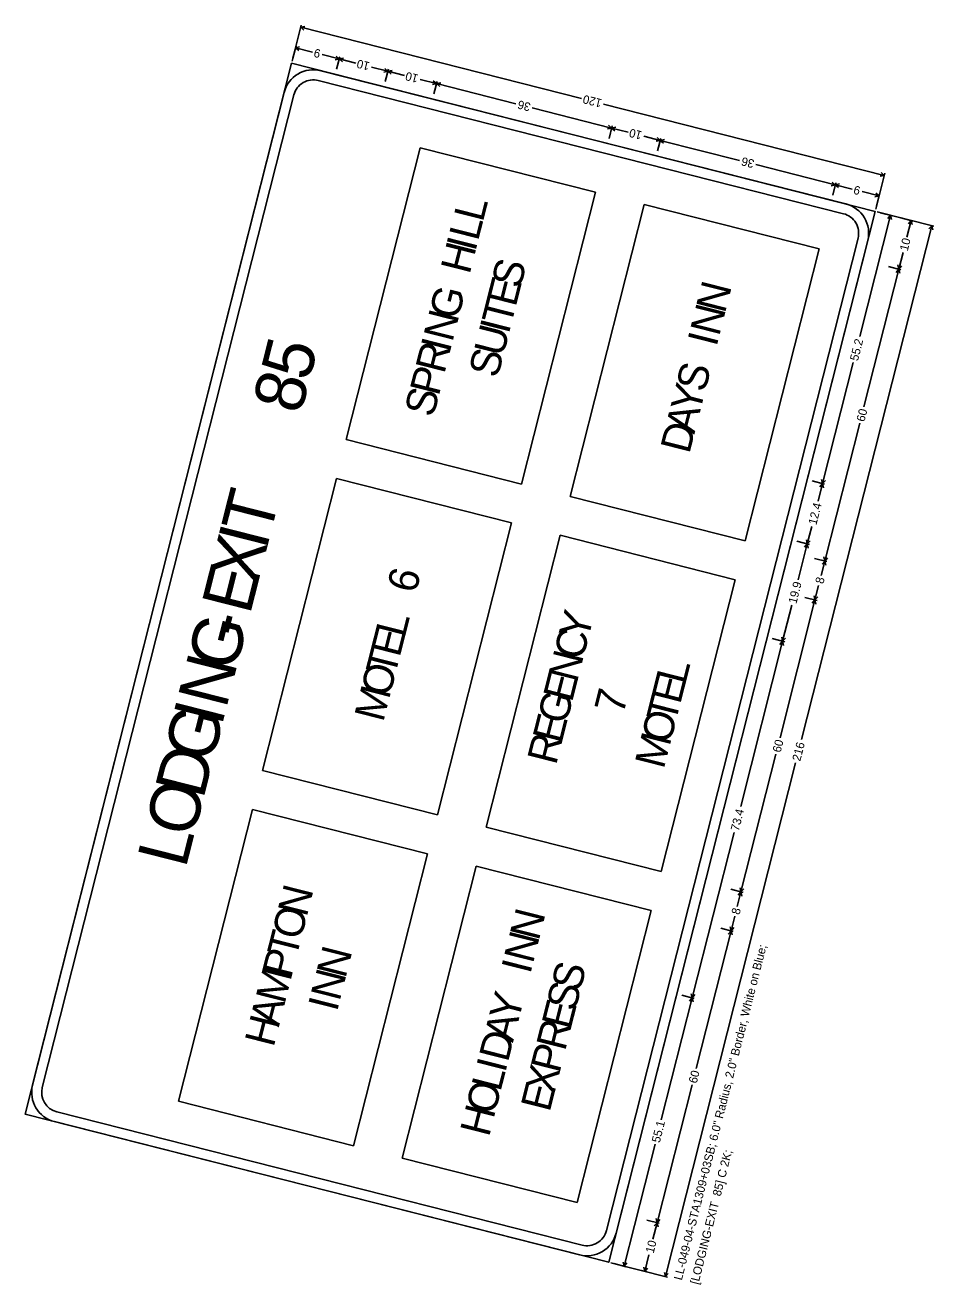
# Model space of a CAD drawing. Extents: x 670257 to 671518, y 737783 to 738188.
# Drawn here: x 670629.61 to 670656.02, y 738032.49 to 738069.09 of the extents above; entities that cross this region are included whole.
import ezdxf

# ---------------------------------------------------------------- set-up
doc = ezdxf.new("R2010")
doc.units = 0
doc.layers.add('R_SIGN', color=7, linetype='Continuous')

msp = doc.modelspace()

# ---------------------------------------------------------------- linework, layer by layer
at = {"layer": 'R_SIGN'}
for p, q in [((670637.631, 738069.092), (670637.366, 738068.045)), ((670637.736, 738069.059), (670637.616, 738069.032)), ((670645.776, 738066.963), (670637.616, 738069.032)), ((670637.709, 738068.952), (670637.616, 738069.032)), ((670637.479, 738068.494), (670637.388, 738068.135)), ((670637.585, 738068.461), (670637.464, 738068.434)), ((670637.958, 738068.309), (670637.464, 738068.434)), ((670637.558, 738068.354), (670637.464, 738068.434)), ((670638.242, 738068.237), (670638.736, 738068.112)), ((670638.616, 738068.085), (670638.736, 738068.112)), ((670638.643, 738068.192), (670638.736, 738068.112)), ((670638.752, 738068.171), (670638.66, 738067.812)), ((670638.857, 738068.138), (670638.736, 738068.112)), ((670639.217, 738067.99), (670638.736, 738068.112)), ((670638.83, 738068.031), (670638.736, 738068.112)), ((670639.669, 738067.875), (670640.15, 738067.753)), ((670640.029, 738067.727), (670640.15, 738067.753)), ((670640.057, 738067.834), (670640.15, 738067.753)), ((670640.165, 738067.813), (670640.074, 738067.454)), ((670640.271, 738067.779), (670640.15, 738067.753)), ((670640.631, 738067.631), (670640.15, 738067.753)), ((670640.243, 738067.672), (670640.15, 738067.753)), ((670641.083, 738067.516), (670641.564, 738067.395)), ((670641.443, 738067.368), (670641.564, 738067.395)), ((670641.47, 738067.475), (670641.564, 738067.395)), ((670641.579, 738067.454), (670641.488, 738067.095)), ((670641.684, 738067.421), (670641.564, 738067.395)), ((670643.87, 738066.81), (670641.564, 738067.395)), ((670641.657, 738067.314), (670641.564, 738067.395)), ((670644.346, 738066.689), (670646.652, 738066.104)), ((670646.419, 738066.8), (670654.579, 738064.73)), ((670646.559, 738066.185), (670646.652, 738066.104)), ((670646.532, 738066.078), (670646.652, 738066.104)), ((670646.668, 738066.164), (670646.577, 738065.805)), ((670646.773, 738066.13), (670646.652, 738066.104)), ((670647.133, 738065.982), (670646.652, 738066.104)), ((670646.746, 738066.023), (670646.652, 738066.104)), ((670647.585, 738065.867), (670648.066, 738065.745)), ((670647.973, 738065.826), (670648.066, 738065.745)), ((670648.081, 738065.805), (670647.99, 738065.446)), ((670638.94, 738057.051), (670641.091, 738065.532)), ((670641.091, 738065.532), (670646.18, 738064.242)), ((670647.945, 738065.719), (670648.066, 738065.745)), ((670648.187, 738065.772), (670648.066, 738065.745)), ((670650.372, 738065.16), (670648.066, 738065.745)), ((670648.159, 738065.665), (670648.066, 738065.745)), ((670650.849, 738065.04), (670653.155, 738064.455)), ((670654.594, 738064.79), (670654.328, 738063.743)), ((670654.458, 738064.704), (670654.579, 738064.73)), ((670654.485, 738064.811), (670654.579, 738064.73)), ((670653.034, 738064.428), (670653.155, 738064.455)), ((670653.061, 738064.535), (670653.155, 738064.455)), ((670653.17, 738064.514), (670653.079, 738064.156)), ((670653.17, 738064.514), (670653.079, 738064.156)), ((670653.275, 738064.481), (670653.155, 738064.455)), ((670653.649, 738064.329), (670653.155, 738064.455)), ((670653.248, 738064.374), (670653.155, 738064.455)), ((670646.18, 738064.242), (670644.029, 738055.76)), ((670653.933, 738064.257), (670654.427, 738064.132)), ((670654.307, 738064.106), (670654.427, 738064.132)), ((670654.334, 738064.213), (670654.427, 738064.132)), ((670654.442, 738064.192), (670654.351, 738063.833)), ((670645.443, 738055.402), (670647.594, 738063.883)), ((670647.594, 738063.883), (670652.683, 738062.592)), ((670656.018, 738063.251), (670654.373, 738063.668)), ((670654.822, 738063.554), (670654.463, 738063.645)), ((670652.172, 738048.336), (670655.959, 738063.266)), ((670653.87, 738060.052), (670654.762, 738063.57)), ((670654.681, 738063.476), (670654.762, 738063.57)), ((670654.788, 738063.449), (670654.762, 738063.57)), ((670655.42, 738063.403), (670655.061, 738063.494)), ((670655.238, 738062.937), (670655.36, 738063.418)), ((670655.28, 738063.324), (670655.36, 738063.418)), ((670655.387, 738063.297), (670655.36, 738063.418)), ((670655.878, 738063.173), (670655.959, 738063.266)), ((670655.985, 738063.146), (670655.959, 738063.266)), ((670652.683, 738062.592), (670650.531, 738054.111)), ((670655.124, 738062.485), (670655.002, 738062.004)), ((670653.986, 738058.001), (670655.002, 738062.004)), ((670655.062, 738061.989), (670654.703, 738062.08)), ((670655.062, 738061.989), (670654.703, 738062.08)), ((670654.921, 738061.911), (670655.002, 738062.004)), ((670654.975, 738062.125), (670655.002, 738062.004)), ((670655.082, 738062.098), (670655.002, 738062.004)), ((670655.028, 738061.884), (670655.002, 738062.004)), ((670653.677, 738059.291), (670652.785, 738055.774)), ((670653.866, 738057.526), (670652.851, 738053.523)), ((670644.029, 738055.76), (670638.94, 738057.051)), ((670636.502, 738047.438), (670638.653, 738055.92)), ((670638.653, 738055.92), (670643.742, 738054.629)), ((670652.845, 738055.759), (670652.486, 738055.85)), ((670652.845, 738055.759), (670652.486, 738055.85)), ((670652.656, 738055.266), (670652.785, 738055.774)), ((670652.704, 738055.68), (670652.785, 738055.774)), ((670652.758, 738055.894), (670652.785, 738055.774)), ((670652.865, 738055.867), (670652.785, 738055.774)), ((670652.811, 738055.653), (670652.785, 738055.774)), ((670650.531, 738054.111), (670645.443, 738055.402)), ((670643.742, 738054.629), (670641.591, 738046.148)), ((670652.469, 738054.528), (670652.34, 738054.021)), ((670643.005, 738045.789), (670645.156, 738054.271)), ((670645.156, 738054.271), (670650.245, 738052.98)), ((670652.4, 738054.006), (670652.041, 738054.097)), ((670652.314, 738054.141), (670652.34, 738054.021)), ((670652.421, 738054.114), (670652.34, 738054.021)), ((670652.076, 738052.978), (670652.34, 738054.021)), ((670652.26, 738053.927), (670652.34, 738054.021)), ((670652.367, 738053.9), (670652.34, 738054.021)), ((670652.91, 738053.508), (670652.551, 738053.599)), ((670652.743, 738053.1), (670652.851, 738053.523)), ((670652.77, 738053.429), (670652.851, 738053.523)), ((670652.824, 738053.643), (670652.851, 738053.523)), ((670652.931, 738053.616), (670652.851, 738053.523)), ((670652.877, 738053.402), (670652.851, 738053.523)), ((670650.245, 738052.98), (670648.094, 738044.499)), ((670652.671, 738052.815), (670652.564, 738052.392)), ((670651.549, 738048.389), (670652.564, 738052.392)), ((670652.624, 738052.377), (670652.265, 738052.468)), ((670652.483, 738052.298), (670652.564, 738052.392)), ((670652.537, 738052.512), (670652.564, 738052.392)), ((670652.644, 738052.485), (670652.564, 738052.392)), ((670652.59, 738052.271), (670652.564, 738052.392)), ((670651.888, 738052.237), (670651.623, 738051.194)), ((670650.406, 738046.393), (670651.623, 738051.194)), ((670651.683, 738051.179), (670651.324, 738051.27)), ((670651.543, 738051.1), (670651.623, 738051.194)), ((670651.597, 738051.314), (670651.623, 738051.194)), ((670651.704, 738051.287), (670651.623, 738051.194)), ((670651.65, 738051.073), (670651.623, 738051.194)), ((670651.428, 738047.913), (670650.413, 738043.91)), ((670652.001, 738047.663), (670648.215, 738032.733)), ((670641.591, 738046.148), (670636.502, 738047.438)), ((670634.064, 738037.826), (670636.215, 738046.308)), ((670636.215, 738046.308), (670641.304, 738045.017)), ((670648.094, 738044.499), (670643.005, 738045.789)), ((670650.213, 738045.633), (670648.995, 738040.832)), ((670641.304, 738045.017), (670639.153, 738036.535)), ((670640.567, 738036.177), (670642.718, 738044.658)), ((670642.718, 738044.658), (670647.807, 738043.368)), ((670650.473, 738043.895), (670650.114, 738043.986)), ((670650.305, 738043.488), (670650.413, 738043.91)), ((670650.332, 738043.817), (670650.413, 738043.91)), ((670650.386, 738044.031), (670650.413, 738043.91)), ((670650.493, 738044.004), (670650.413, 738043.91)), ((670650.439, 738043.79), (670650.413, 738043.91)), ((670647.807, 738043.368), (670645.656, 738034.886)), ((670650.233, 738043.203), (670650.126, 738042.78)), ((670649.111, 738038.777), (670650.126, 738042.78)), ((670650.186, 738042.764), (670649.827, 738042.855)), ((670650.045, 738042.686), (670650.126, 738042.78)), ((670650.1, 738042.9), (670650.126, 738042.78)), ((670650.207, 738042.873), (670650.126, 738042.78)), ((670650.152, 738042.659), (670650.126, 738042.78)), ((670648.969, 738040.953), (670648.995, 738040.832)), ((670649.076, 738040.926), (670648.995, 738040.832)), ((670648.097, 738037.292), (670648.995, 738040.832)), ((670649.055, 738040.817), (670648.696, 738040.908)), ((670648.915, 738040.739), (670648.995, 738040.832)), ((670649.022, 738040.712), (670648.995, 738040.832)), ((670648.99, 738038.301), (670647.975, 738034.298)), ((670639.153, 738036.535), (670634.064, 738037.826)), ((670647.916, 738036.577), (670647.018, 738033.036)), ((670645.656, 738034.886), (670640.567, 738036.177)), ((670648.035, 738034.283), (670647.676, 738034.374)), ((670647.948, 738034.419), (670647.975, 738034.298)), ((670648.055, 738034.392), (670647.975, 738034.298)), ((670647.853, 738033.817), (670647.975, 738034.298)), ((670647.894, 738034.205), (670647.975, 738034.298)), ((670648.001, 738034.178), (670647.975, 738034.298)), ((670647.738, 738033.365), (670647.616, 738032.885)), ((670648.274, 738032.718), (670646.629, 738033.135)), ((670647.078, 738033.021), (670646.719, 738033.112)), ((670646.992, 738033.157), (670647.018, 738033.036)), ((670647.099, 738033.13), (670647.018, 738033.036)), ((670647.676, 738032.869), (670647.317, 738032.96)), ((670647.59, 738033.005), (670647.616, 738032.885)), ((670647.697, 738032.978), (670647.616, 738032.885)), ((670648.188, 738032.853), (670648.215, 738032.733)), ((670648.295, 738032.826), (670648.215, 738032.733))]:
    msp.add_line(p, q, dxfattribs=at)
for points in [[(670646.569, 738033.15), (670654.313, 738063.683), (670637.35, 738067.986), (670629.606, 738037.452), (670646.569, 738033.15), (670646.569, 738033.15)], [(670638.198, 738067.77), (670653.465, 738063.898)], [(670653.393, 738063.616), (670638.127, 738067.488)], [(670629.822, 738038.3), (670637.135, 738067.137)], [(670637.418, 738067.066), (670630.104, 738038.229)], [(670646.502, 738034.07), (670653.815, 738062.907)], [(670654.098, 738062.835), (670646.784, 738033.998)], [(670630.526, 738037.52), (670645.793, 738033.648)], [(670645.721, 738033.365), (670630.455, 738037.237)]]:
    msp.add_lwpolyline(points, dxfattribs=at)
for centre, radius, start, end in [((670637.983, 738066.922), 0.875, 75.7686, 165.7688), ((670637.983, 738066.922), 0.583, 75.7686, 165.7688), ((670653.25, 738063.05), 0.583, 345.7686, 75.7688), ((670653.25, 738063.05), 0.875, 345.7686, 75.7688), ((670630.67, 738038.085), 0.875, 165.7688, 255.7684), ((670630.67, 738038.085), 0.583, 165.7688, 255.7684), ((670645.936, 738034.213), 0.875, 255.7684, 345.7686), ((670645.936, 738034.213), 0.583, 255.7684, 345.7686)]:
    msp.add_arc(centre, radius, start, end, dxfattribs=at)

# ---------------------------------------------------------------- texts
for s, height, rotation, p in [('9', 0.247, 165.7688, (670638.213, 738068.372)), ('10', 0.2469, 165.7688, (670639.639, 738068.01)), ('10', 0.2469, 165.7688, (670641.053, 738067.651)), ('36', 0.2469, 165.7688, (670644.317, 738066.824)), ('120', 0.2469, 165.7688, (670646.389, 738066.935)), ('10', 0.2469, 165.7688, (670647.556, 738066.002)), ('36', 0.2469, 165.7688, (670650.819, 738065.174)), ('9', 0.247, 165.7688, (670653.903, 738064.392)), ('L', 0.875, 75.7686, (670642.907, 738063.348)), ('L', 0.875, 75.7686, (670642.767, 738062.796)), ('I', 0.875, 75.7686, (670642.689, 738062.491)), ('10', 0.2469, 75.7686, (670655.259, 738062.515)), ('H', 0.875, 75.7686, (670642.522, 738061.829)), ('S', 0.875, 75.7686, (670643.996, 738061.415)), ('E', 0.875, 75.7686, (670643.861, 738060.881)), ('G', 0.875, 75.7686, (670642.186, 738060.506)), ('N', 0.875, 75.7686, (670649.944, 738060.692)), ('T', 0.875, 75.7686, (670643.721, 738060.329)), ('N', 0.875, 75.7686, (670642.023, 738059.862)), ('N', 0.875, 75.7686, (670649.776, 738060.03)), ('U', 0.875, 75.7686, (670643.493, 738059.43)), ('I', 0.875, 75.7686, (670643.661, 738060.092)), ('5', 1.458, 75.7686, (670637.858, 738058.717)), ('I', 0.875, 75.7686, (670641.945, 738059.556)), ('I', 0.875, 75.7686, (670649.699, 738059.725)), ('55.2', 0.2469, 75.7686, (670653.812, 738059.321)), ('R', 0.875, 75.7686, (670641.788, 738058.937)), ('S', 0.875, 75.7686, (670643.336, 738058.811)), ('S', 0.875, 75.7686, (670649.363, 738058.402)), ('8', 1.458, 75.7686, (670637.614, 738057.756)), ('P', 0.875, 75.7686, (670641.625, 738058.293)), ('S', 0.875, 75.7686, (670641.468, 738057.674)), ('Y', 0.875, 75.7686, (670649.206, 738057.783)), ('A', 0.875, 75.7686, (670649.055, 738057.189)), ('60', 0.2469, 75.7686, (670654.001, 738057.555)), ('D', 0.875, 75.7686, (670648.909, 738056.612)), ('T', 1.458, 75.7686, (670636.714, 738054.208)), ('12.4', 0.2469, 75.7686, (670652.604, 738054.557)), ('I', 1.458, 75.7686, (670636.614, 738053.812)), ('X', 1.458, 75.7686, (670636.352, 738052.78)), ('E', 1.458, 75.7686, (670636.137, 738051.932)), ('6', 0.875, 75.7686, (670640.96, 738052.559)), ('8', 0.247, 75.7686, (670652.806, 738052.844)), ('19.9', 0.2469, 75.7686, (670652.023, 738052.266)), ('-', 1.458, 75.7686, (670635.962, 738051.239)), ('Y', 0.875, 75.7686, (670645.955, 738051.193)), ('G', 1.458, 75.7686, (670635.718, 738050.278)), ('E', 0.875, 75.7686, (670640.489, 738050.702)), ('L', 0.875, 75.7686, (670640.636, 738051.278)), ('C', 0.875, 75.7686, (670645.809, 738050.616)), ('T', 0.875, 75.7686, (670640.349, 738050.15)), ('N', 0.875, 75.7686, (670645.645, 738049.972)), ('N', 1.458, 75.7686, (670635.445, 738049.204)), ('O', 0.875, 75.7686, (670640.197, 738049.548)), ('L', 0.875, 75.7686, (670648.79, 738049.914)), ('E', 0.875, 75.7686, (670645.499, 738049.395)), ('E', 0.875, 75.7686, (670648.644, 738049.338)), ('M', 0.875, 75.7686, (670640.012, 738048.819)), ('7', 0.875, 75.7686, (670646.988, 738049.04)), ('I', 1.458, 75.7686, (670635.316, 738048.695)), ('G', 0.875, 75.7686, (670645.335, 738048.75)), ('T', 0.875, 75.7686, (670648.504, 738048.786)), ('G', 1.458, 75.7686, (670635.044, 738047.62)), ('E', 0.875, 75.7686, (670645.193, 738048.191)), ('O', 0.875, 75.7686, (670648.351, 738048.184)), ('R', 0.875, 75.7686, (670645.036, 738047.571)), ('M', 0.875, 75.7686, (670648.166, 738047.455)), ('60', 0.2469, 75.7686, (670651.563, 738047.943)), ('216', 0.2469, 75.7686, (670652.136, 738047.692)), ('D', 1.458, 75.7686, (670634.779, 738046.574)), ('O', 1.458, 75.7686, (670634.495, 738045.458)), ('73.4', 0.2469, 75.7686, (670650.348, 738045.662)), ('L', 1.458, 75.7686, (670634.269, 738044.567)), ('N', 0.875, 75.7686, (670637.786, 738043.156)), ('O', 0.875, 75.7686, (670637.616, 738042.486)), ('N', 0.875, 75.7686, (670644.531, 738042.465)), ('8', 0.247, 75.7686, (670650.368, 738043.232)), ('T', 0.875, 75.7686, (670637.48, 738041.952)), ('N', 0.875, 75.7686, (670644.363, 738041.804)), ('P', 0.875, 75.7686, (670637.334, 738041.375)), ('N', 0.875, 75.7686, (670638.913, 738041.372)), ('LL-049-04-STA1309+03SB; 6.0" Radius, 2.0" Border, White on Blue; ', 0.24688, 75.7686, (670648.693, 738032.611)), ('M', 0.875, 75.7686, (670637.145, 738040.629)), ('N', 0.875, 75.7686, (670638.745, 738040.71)), ('I', 0.875, 75.7686, (670644.286, 738041.498)), ('S', 0.875, 75.7686, (670645.737, 738040.991)), ('Y', 0.875, 75.7686, (670643.933, 738040.107)), ('S', 0.875, 75.7686, (670645.591, 738040.414)), ('A', 0.875, 75.7686, (670636.977, 738039.967)), ('I', 0.875, 75.7686, (670638.668, 738040.405)), ('E', 0.875, 75.7686, (670645.455, 738039.879)), ('H', 0.875, 75.7686, (670636.826, 738039.373)), ('A', 0.875, 75.7686, (670643.783, 738039.514)), ('D', 0.875, 75.7686, (670643.636, 738038.937)), ('R', 0.875, 75.7686, (670645.298, 738039.26)), ('P', 0.875, 75.7686, (670645.135, 738038.616)), ('I', 0.875, 75.7686, (670643.559, 738038.632)), ('X', 0.875, 75.7686, (670644.978, 738037.997)), ('O', 0.875, 75.7686, (670643.249, 738037.41)), ('L', 0.875, 75.7686, (670643.419, 738038.08)), ('E', 0.875, 75.7686, (670644.849, 738037.488)), ('60', 0.2469, 75.7686, (670649.125, 738038.331)), ('H', 0.875, 75.7686, (670643.086, 738036.766)), ('55.1', 0.2469, 75.7686, (670648.051, 738036.606)), ('[LODGING-EXIT  85] C 2K; ', 0.24688, 75.7686, (670649.172, 738032.49)), ('10', 0.2469, 75.7686, (670647.873, 738033.395))]:
    msp.add_text(s, height=height, rotation=rotation, dxfattribs=at).set_placement(p)

doc.saveas('drawing.dxf')
